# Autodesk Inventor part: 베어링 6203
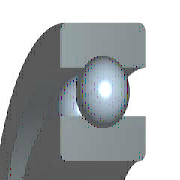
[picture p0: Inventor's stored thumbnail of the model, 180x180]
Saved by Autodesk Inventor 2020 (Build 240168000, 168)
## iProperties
IsCustomPart: 0
Created: 2016-05
Part Number: 베어링 6203
Material: 강, 연강
Description: 깊은 그루브 볼 베어링
Document SubType Name: Modeling
Standard: KS B 2023
Designer: mduedu
Standards Organization: KS
Language: ko-KR
Size Designation: 6203 - 17 x 40 x 12
Categories: <MemberInstance><Categories><Category DisplayName="샤프트 부품" InternalName="7f7aeb1f-a693-4053-b835-cee3144e0d98" Mnemonic="SHFT"><Category DisplayName="베어링" Inter
Density: 1 g/cm^3
Appearance: 노란색
Author: mduedu
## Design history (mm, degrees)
sketch "스케치" dims "d0" = 5.98 (= -0.26 x WD + 0.26 x BD)
  geometry: L1 (3.01, 14.25)-(8.99, 14.25); L2 (6, 14.25)-(6, 11.26); L3 (6, 14.25)-(6, 17.24); L4 (3.778, 12.249)-(0, 12.249); L5 (0, 8.5)-(12, 8.5); L6 (3.778, 16.251)-(0, 16.251); L7 (0, 20)-(12, 20); L8 (12, 8.5)-(12, 12.249); L9 (8.222, 12.249)-(12, 12.249); L10 (8.222, 16.251)-(12, 16.251); L11 (12, 20)-(12, 16.251); L12 (-1.4, 0)-(8.4, 0) reference; L13 (0, -0.3)-(0, 5.3) reference
  constraints: 22 end point, 4 point on line, 2 collinear, 2 perpendicular, 2 symmetric about line, 1 midpoint, 1 parallel, 14 other
  dimensions: "d9" = 17 diameter of L5 L12 (= WD); "d11" = 40 diameter of L7 L12 (= BD); "d12" = 12 distance between parallel lines of L8 L13 (= KB); "d13" = 24.498 diameter of L9 L12 (= 0.326 x BD + 0.674 x WD)
revolve "본체" stored, may be unused: angle "d6" = 90 deg
revolve "볼" stored, may be unused: angle "d7" = 90 deg
pattern_circular "IDS_ARRAYBALL[SIMPL:T]" dims angle "d3" = 360 deg
body "Solid1"
fillet "모깎기1" dims "d1" = 0.6 (= KRS)
other parameters: "WD" = 17 [user parameter; used in 5 equation terms], "BD" = 40 [user parameter; used in 5 equation terms], "KB" = 12 [user parameter; used in 1 equation term], "KRS" = 0.6 [user parameter; used in 1 equation term], "d4" = 0, "d5" = 0, "d8" = 0, "d14" = 0, "d15" = 0, "BBA" = 0 [user parameter], "BC0" = 4750000 [user parameter], "BC" = 9560000 [user parameter], "WR" = 8.5 (= 0.5 x WD) [user parameter]
